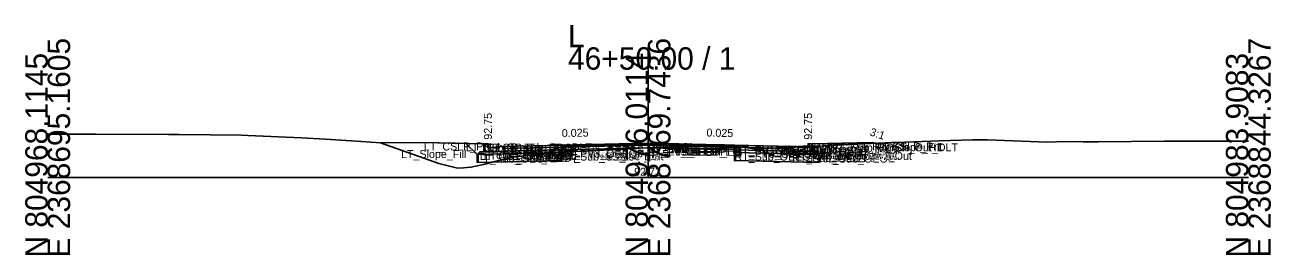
# Model space of a CAD drawing. Extents: x -26 to 8153, y -10 to 9520.
# Drawn here: x 3997.2 to 4152.8, y 3490.3 to 3519.1 of the extents above; entities that cross this region are included whole.
import ezdxf

# ---------------------------------------------------------------- set-up
doc = ezdxf.new("R2010")
doc.units = 0
for name, color, linetype in [('Exist CMT Pavement', 7, 'Continuous'), ('Exist Cross Section Cell', 7, 'Continuous'), ('Exist XS Center Line Elevation Label', 7, 'Continuous'), ('Exist XS Ground Line', 7, 'Continuous'), ('Prop CMT Conc Surface', 7, 'Continuous'), ('Prop CMT Concrete Structures', 7, 'Continuous'), ('Prop CMT Pvmt Course 1', 7, 'Continuous'), ('Prop CMT Pvmt Course 1 CG', 7, 'Continuous'), ('Prop CMT Pvmt Course 1 Wedge', 7, 'Continuous'), ('Prop CMT Pvmt Course 2', 7, 'Continuous'), ('Prop CMT Pvmt Course 2 Wedge', 7, 'Continuous'), ('Prop CMT Pvmt Course 3', 7, 'Continuous'), ('Prop CMT Pvmt Course 3 Wedge', 7, 'Continuous'), ('Prop CMT Pvmt Surface', 7, 'Continuous'), ('Prop CMT Pvmt Wedge Surface 1', 7, 'Continuous'), ('Prop CMT Pvmt Wedge Surface 2', 7, 'Continuous'), ('Prop CMT Pvmt Wedge Surface 3', 7, 'Continuous'), ('Prop CMT Shallow Undercut', 7, 'Continuous'), ('Prop CMT Shallow Undercut Boundary', 7, 'Continuous'), ('Prop CMT Slope Grass', 7, 'Continuous'), ('Prop CMT Subgrade Earthwork', 7, 'Continuous'), ('Prop XS Earthwork Shape', 7, 'Continuous'), ('Prop XS Hydro Elevations', 7, 'Continuous'), ('Prop XS SE Text', 7, 'Continuous'), ('Prop XS Side Slope Text', 7, 'Continuous'), ('Prop XS Subgrade Earthwork', 7, 'Continuous'), ('Scratch_Level_2', 7, 'Continuous'), ('Scratch_Level_5', 7, 'Continuous'), ('Scratch_Level_6', 7, 'Continuous')]:
    doc.layers.add(name, color=color, linetype=linetype)

msp = doc.modelspace()

# ---------------------------------------------------------------- linework, layer by layer
at = {"layer": 'Exist CMT Pavement'}
for p, q in [((4064.2, 3503.18), (4070.31, 3503.47)), ((4070.31, 3503.47), (4074.83, 3503.72)), ((4074.83, 3503.72), (4081.98, 3503.93)), ((4081.98, 3503.93), (4085.8, 3504))]:
    msp.add_line(p, q, dxfattribs=at)
at = {"layer": 'Exist Cross Section Cell'}
for p, q in [((4075, 3500), (4075, 3516.31)), ((4000, 3500), (4075, 3500)), ((4075, 3500), (4150, 3500))]:
    msp.add_line(p, q, dxfattribs=at)
at = {"layer": 'Exist XS Ground Line'}
for p, q in [((4000, 3505.44), (4004.88, 3505.42)), ((4004.88, 3505.42), (4005.99, 3505.42)), ((4005.99, 3505.42), (4015.08, 3505.39)), ((4015.08, 3505.39), (4016.44, 3505.38)), ((4016.44, 3505.38), (4024.18, 3505.3)), ((4024.18, 3505.3), (4025, 3505.29)), ((4025, 3505.29), (4031.71, 3504.96)), ((4031.71, 3504.96), (4034.66, 3504.83)), ((4034.66, 3504.83), (4037.96, 3504.59)), ((4037.96, 3504.59), (4041.56, 3504.36)), ((4096.93, 3504), (4105.45, 3504.41)), ((4105.45, 3504.41), (4106.02, 3504.4)), ((4106.02, 3504.4), (4111.41, 3504.62)), ((4111.41, 3504.62), (4115.55, 3504.75)), ((4115.55, 3504.75), (4117.4, 3504.75)), ((4117.4, 3504.75), (4124.88, 3504.44)), ((4124.88, 3504.44), (4127.26, 3504.51)), ((4127.26, 3504.51), (4129.36, 3504.5)), ((4129.36, 3504.5), (4131.25, 3504.47)), ((4131.25, 3504.47), (4139.53, 3504.57)), ((4139.53, 3504.57), (4141.49, 3504.57)), ((4141.49, 3504.57), (4150, 3504.55)), ((4041.56, 3504.36), (4047.69, 3502.18)), ((4060.23, 3502.8), (4064.2, 3503.18)), ((4064.2, 3503.18), (4070.31, 3503.47)), ((4070.31, 3503.47), (4074.83, 3503.72)), ((4074.83, 3503.72), (4081.98, 3503.93)), ((4081.98, 3503.93), (4085.8, 3504)), ((4085.8, 3504), (4088.28, 3503.61)), ((4088.28, 3503.61), (4088.58, 3503.58)), ((4088.58, 3503.58), (4094.39, 3503.94)), ((4094.39, 3503.94), (4095.39, 3503.95)), ((4095.39, 3503.95), (4096.93, 3504)), ((4047.69, 3502.18), (4048.86, 3501.77)), ((4048.86, 3501.77), (4051.2, 3501.18)), ((4051.97, 3501.22), (4052.87, 3501.3)), ((4052.87, 3501.3), (4054.43, 3501.66)), ((4054.43, 3501.66), (4057.83, 3502.53)), ((4057.83, 3502.53), (4060.23, 3502.8)), ((4051.2, 3501.18), (4051.97, 3501.22))]:
    msp.add_line(p, q, dxfattribs=at)
at = {"layer": 'Prop CMT Conc Surface'}
for points in [[(4055, 3503.75), (4055, 3504.25), (4054.5, 3504.25)], [(4057, 3503.88), (4055, 3503.75)], [(4093, 3503.88), (4095, 3503.75)], [(4095, 3503.75), (4095, 3504.25), (4095.5, 3504.25)]]:
    msp.add_lwpolyline(points, dxfattribs=at)
at = {"layer": 'Prop CMT Concrete Structures'}
for points in [[(4057, 3503.88), (4055, 3503.75), (4055, 3504.25), (4054.5, 3504.25)], [(4054.5, 3504.25), (4054.5, 3503.23), (4057, 3503.29)], [(4057, 3503.29), (4057, 3503.88)], [(4093, 3503.88), (4095, 3503.75), (4095, 3504.25), (4095.5, 3504.25)], [(4095.5, 3504.25), (4095.5, 3503.23), (4093, 3503.29)], [(4093, 3503.29), (4093, 3503.88)]]:
    msp.add_lwpolyline(points, dxfattribs=at)
at = {"layer": 'Prop CMT Pvmt Course 1'}
for points in [[(4075, 3504.33), (4057, 3503.88)], [(4057, 3503.88), (4057, 3503.63)], [(4057, 3503.63), (4064.2, 3503.81)], [(4064.2, 3503.93), (4075, 3504.2)], [(4064.2, 3503.81), (4064.2, 3503.93)], [(4075, 3504.08), (4075, 3504.33)], [(4075, 3504.33), (4093, 3503.88)], [(4075, 3504.08), (4075, 3504.33)], [(4075, 3504.2), (4075, 3504.08), (4075, 3504.08)], [(4085.8, 3503.93), (4075, 3504.2)], [(4075, 3504.2), (4075, 3504.08), (4075, 3504.08)], [(4085.8, 3503.81), (4085.8, 3503.93)], [(4093, 3503.63), (4085.8, 3503.81)], [(4093, 3503.88), (4093, 3503.63)]]:
    msp.add_lwpolyline(points, dxfattribs=at)
at = {"layer": 'Prop CMT Pvmt Course 1 CG'}
for points in [[(4057, 3503.29), (4054, 3503.22), (4053.66, 3502.88)], [(4053.66, 3502.88), (4057, 3502.96)], [(4057, 3502.96), (4057, 3503.29)], [(4093, 3503.29), (4096, 3503.22), (4096.34, 3502.88)], [(4093, 3502.96), (4093, 3503.29)], [(4096.34, 3502.88), (4093, 3502.96)]]:
    msp.add_lwpolyline(points, dxfattribs=at)
at = {"layer": 'Prop CMT Pvmt Course 1 Wedge'}
for points in [[(4075, 3504.2), (4064.2, 3503.93)], [(4075, 3504.2), (4085.8, 3503.93)]]:
    msp.add_lwpolyline(points, dxfattribs=at)
at = {"layer": 'Prop CMT Pvmt Course 2'}
for points in [[(4064.2, 3503.81), (4057, 3503.63)], [(4057, 3503.63), (4057, 3503.3)], [(4057, 3503.3), (4064.2, 3503.48)], [(4064.2, 3503.48), (4064.2, 3503.81)], [(4085.8, 3503.48), (4085.8, 3503.81)], [(4085.8, 3503.81), (4093, 3503.63)], [(4093, 3503.3), (4085.8, 3503.48)], [(4093, 3503.63), (4093, 3503.3)]]:
    msp.add_lwpolyline(points, dxfattribs=at)
at = {"layer": 'Prop CMT Pvmt Course 2 Wedge'}
for points in [[(4075, 3504.08), (4064.2, 3503.81)], [(4075, 3504.08), (4085.8, 3503.81)]]:
    msp.add_lwpolyline(points, dxfattribs=at)
at = {"layer": 'Prop CMT Pvmt Course 3'}
for points in [[(4064.2, 3503.48), (4057, 3503.3)], [(4057, 3503.3), (4057, 3502.96)], [(4057, 3502.96), (4064.2, 3503.14)], [(4064.2, 3503.14), (4064.2, 3503.48)], [(4085.8, 3503.48), (4093, 3503.3)], [(4085.8, 3503.14), (4085.8, 3503.48)], [(4093, 3502.96), (4085.8, 3503.14)], [(4093, 3503.3), (4093, 3502.96)]]:
    msp.add_lwpolyline(points, dxfattribs=at)
at = {"layer": 'Prop CMT Pvmt Course 3 Wedge'}
for points in [[(4075, 3503.75), (4064.2, 3503.48)], [(4075, 3503.75), (4085.8, 3503.48)]]:
    msp.add_lwpolyline(points, dxfattribs=at)
at = {"layer": 'Prop CMT Pvmt Surface'}
for points in [[(4075, 3504.33), (4057, 3503.88)], [(4075, 3504.33), (4093, 3503.88)]]:
    msp.add_lwpolyline(points, dxfattribs=at)
at = {"layer": 'Prop CMT Pvmt Wedge Surface 1'}
for points in [[(4057, 3503.63), (4057, 3503.88)], [(4064.2, 3503.81), (4057, 3503.63)], [(4075, 3504.2), (4064.2, 3503.93)], [(4064.2, 3503.93), (4064.2, 3503.81)], [(4075, 3504.2), (4085.8, 3503.93)], [(4085.8, 3503.93), (4085.8, 3503.81)], [(4085.8, 3503.81), (4093, 3503.63)], [(4093, 3503.63), (4093, 3503.88)]]:
    msp.add_lwpolyline(points, dxfattribs=at)
at = {"layer": 'Prop CMT Pvmt Wedge Surface 2'}
for points in [[(4075, 3504.08), (4057, 3503.63)], [(4057, 3503.63), (4057, 3503.88)], [(4075, 3504.08), (4093, 3503.63)], [(4093, 3503.63), (4093, 3503.88)]]:
    msp.add_lwpolyline(points, dxfattribs=at)
at = {"layer": 'Prop CMT Pvmt Wedge Surface 3'}
for points in [[(4057, 3503.3), (4057, 3503.88)], [(4075, 3503.75), (4057, 3503.3)], [(4075, 3503.75), (4093, 3503.3)], [(4093, 3503.3), (4093, 3503.88)]]:
    msp.add_lwpolyline(points, dxfattribs=at)
at = {"layer": 'Prop CMT Shallow Undercut'}
for p, q in [((4085.8, 3503.14), (4085.8, 3502.14)), ((4096.34, 3502.88), (4085.8, 3503.14)), ((4096.34, 3501.88), (4096.34, 3502.88)), ((4085.8, 3502.14), (4096.34, 3501.88))]:
    msp.add_line(p, q, dxfattribs=at)
msp.add_lwpolyline([(4055.47, 3501.93), (4064.2, 3502.14), (4064.2, 3503.14), (4063.68, 3503.13), (4060.23, 3502.8), (4057.83, 3502.53)], close=True, dxfattribs=at)
at = {"layer": 'Prop CMT Shallow Undercut Boundary'}
for p, q in [((4053.66, 3502.88), (4053.66, 3501.88)), ((4064.2, 3503.14), (4064.2, 3502.14)), ((4085.8, 3503.14), (4085.8, 3502.14)), ((4096.34, 3502.88), (4096.34, 3501.88)), ((4053.66, 3501.88), (4064.2, 3502.14)), ((4085.8, 3502.14), (4096.34, 3501.88))]:
    msp.add_line(p, q, dxfattribs=at)
at = {"layer": 'Prop CMT Slope Grass'}
for points in [[(4054.5, 3504.25), (4047, 3504.4), (4041.56, 3504.36)], [(4095.5, 3504.25), (4103, 3504.4), (4103.28, 3504.3)]]:
    msp.add_lwpolyline(points, dxfattribs=at)
at = {"layer": 'Prop CMT Subgrade Earthwork'}
for points in [[(4057, 3502.96), (4053.66, 3502.88), (4052.25, 3504.29)], [(4064.2, 3503.14), (4057, 3502.96)], [(4064.2, 3503.14), (4064.22, 3503.18)], [(4085.8, 3503.14), (4085.78, 3504)], [(4085.8, 3503.14), (4093, 3502.96)], [(4093, 3502.96), (4096.34, 3502.88), (4097.75, 3504.29)]]:
    msp.add_lwpolyline(points, dxfattribs=at)
at = {"layer": 'Prop XS Earthwork Shape'}
for points in [[(4047.69, 3502.18), (4048.86, 3501.77), (4051.2, 3501.18), (4051.97, 3501.22), (4052.87, 3501.3), (4054.43, 3501.66), (4055.47, 3501.93), (4053.66, 3501.88), (4053.66, 3502.88), (4052.25, 3504.29), (4047, 3504.4), (4041.56, 3504.36)], [(4103, 3504.4), (4103.28, 3504.3), (4097.48, 3504.03), (4097.75, 3504.29)], [(4057.83, 3502.53), (4060.23, 3502.8), (4063.68, 3503.13), (4057, 3502.96), (4053.66, 3502.88), (4053.66, 3501.88), (4055.47, 3501.93)], [(4057.83, 3502.53), (4060.23, 3502.8), (4063.68, 3503.13), (4064.2, 3503.14), (4064.2, 3502.14), (4055.47, 3501.93)], [(4064.2, 3503.14), (4063.68, 3503.13), (4064.2, 3503.18), (4064.22, 3503.18)], [(4093.18, 3503.87), (4095, 3503.75), (4095, 3503.95), (4095.39, 3503.95), (4096.93, 3504), (4097.48, 3504.03), (4096.34, 3502.88), (4093, 3502.96), (4085.8, 3503.14), (4085.78, 3504), (4085.8, 3504), (4088.28, 3503.61), (4088.58, 3503.58)], [(4096.34, 3502.88), (4096.34, 3501.88), (4085.8, 3502.14), (4085.8, 3503.14), (4093, 3502.96)], [(4093.18, 3503.87), (4095, 3503.75), (4095, 3503.95), (4094.39, 3503.94)]]:
    msp.add_lwpolyline(points, close=True, dxfattribs=at)
at = {"layer": 'Prop XS Subgrade Earthwork'}
for p, q in [((4053.66, 3502.88), (4064.2, 3503.14)), ((4085.8, 3503.14), (4096.34, 3502.88))]:
    msp.add_line(p, q, dxfattribs=at)
at = {"layer": 'Scratch_Level_5'}
for p, q in [((4054.5, 3504.25), (4052.25, 3504.29)), ((4052.25, 3504.29), (4053.66, 3502.88)), ((4053.66, 3502.88), (4054, 3503.22)), ((4054, 3503.22), (4054.5, 3503.23)), ((4054.5, 3503.23), (4054.5, 3504.25)), ((4097.75, 3504.29), (4095.5, 3504.25)), ((4095.5, 3504.25), (4095.5, 3503.23)), ((4095.5, 3503.23), (4096, 3503.22)), ((4096, 3503.22), (4096.34, 3502.88)), ((4096.34, 3502.88), (4097.75, 3504.29))]:
    msp.add_line(p, q, dxfattribs=at)
at = {"layer": 'Scratch_Level_6'}
for p, q in [((4085.8, 3503.14), (4085.8, 3502.14)), ((4096.34, 3502.88), (4085.8, 3503.14)), ((4096.34, 3501.88), (4096.34, 3502.88)), ((4085.8, 3502.14), (4096.34, 3501.88))]:
    msp.add_line(p, q, dxfattribs=at)
msp.add_lwpolyline([(4055.47, 3501.93), (4064.2, 3502.14), (4064.2, 3503.14), (4063.68, 3503.13), (4060.23, 3502.8), (4057.83, 3502.53)], close=True, dxfattribs=at)

# ---------------------------------------------------------------- texts
at = {"layer": 'Exist Cross Section Cell'}
for s, p in [('L', (4065, 3516.31)), ('46+50.00 / 1', (4065, 3513.51))]:
    msp.add_text(s, height=2.8, dxfattribs=at).set_placement(p)
for s, p in [('E 2368695.1605', (4002.8, 3490)), ('E 2368769.7436', (4077.8, 3490)), ('E 2368844.3267', (4152.8, 3490)), ('N 804968.1145', (4000, 3490)), ('N 804976.0114', (4075, 3490)), ('N 804983.9083', (4150, 3490))]:
    msp.add_text(s, height=2.8, rotation=90, dxfattribs=at).set_placement(p)
at = {"layer": 'Exist XS Center Line Elevation Label'}
msp.add_text('92.73', height=1, dxfattribs=at).set_placement((4073.27, 3500.23))
at = {"layer": 'Prop XS Hydro Elevations'}
for p in [(4055.5, 3504.75), (4095.5, 3504.75)]:
    msp.add_text('92.75', height=1, rotation=90, dxfattribs=at).set_placement(p)
at = {"layer": 'Prop XS SE Text'}
for rotation, p in [(1.4321, (4064.24, 3505.06)), (358.5679, (4082.29, 3505.15))]:
    msp.add_text('0.025', height=1, rotation=rotation, dxfattribs=at).set_placement(p)
at = {"layer": 'Prop XS Side Slope Text'}
msp.add_text('3:1', height=1, rotation=341.5651, dxfattribs=at).set_placement((4102.63, 3505.31))
at = {"layer": 'Scratch_Level_2'}
for s, p in [('LT_CSLP_Pnt', (4047, 3503.4)), ('RT_CSLP_Pnt', (4103, 3503.4)), ('LT_Slope_Fill', (4044.14, 3502.45)), ('LT_Sub_Trench_Out_DLT', (4052.25, 3503.29)), ('LT_Sub_OEOP', (4053.66, 3501.88)), ('LT_CG1_Shelf_Out', (4054, 3502.22)), ('LT_CG_Top_BOC', (4054.5, 3503.25)), ('LT_CG_Bot_BOC', (4054.5, 3502.23)), ('LT_CG_Top_Face', (4055, 3503.25)), ('LT_CG_Top_Gut', (4055, 3502.75)), ('LT_PV1_OEOT', (4057, 3502.88)), ('LT_PV2_OEOT', (4057, 3502.63)), ('LT_PV3_OEOT', (4057, 3502.3)), ('LT_CG_Bot_IE', (4057, 3502.29)), ('LT_Sub_OEOT', (4057, 3501.96)), ('LT_PV1_OEEOP', (4064.2, 3502.93)), ('LT_PV2_OEEOP', (4064.2, 3502.81)), ('LT_PV3_OEEOP', (4064.2, 3502.48)), ('LT_PV_OEEOP_EG', (4064.2, 3502.18)), ('LT_Sub_OEEOP', (4064.2, 3502.14)), ('LT_PV_Sub_Tie_Out', (4064.22, 3502.18)), ('PV1_PGL', (4075, 3503.33)), ('RT_PV1_IEEOP', (4075, 3503.2)), ('LT_PV1_IEEOP', (4075, 3503.2)), ('RT_PV2_IEEOP', (4075, 3503.08)), ('LT_PV2_IEEOP', (4075, 3503.08)), ('PV2_PGL', (4075, 3503.08)), ('RT_PV3_IEEOP', (4075, 3502.75)), ('LT_PV3_IEEOP', (4075, 3502.75)), ('RT_PV_IEEOP_EG', (4075, 3502.73)), ('LT_PV_IEEOP_EG', (4075, 3502.73)), ('RT_PV_Sub_Tie_Out', (4085.78, 3503)), ('RT_PV_OEEOP_EG', (4085.8, 3503)), ('RT_PV1_OEEOP', (4085.8, 3502.93)), ('RT_PV2_OEEOP', (4085.8, 3502.81)), ('RT_PV3_OEEOP', (4085.8, 3502.48)), ('RT_Sub_OEEOP', (4085.8, 3502.14)), ('RT_PV1_OEOT', (4093, 3502.88)), ('RT_PV2_OEOT', (4093, 3502.63)), ('RT_PV3_OEOT', (4093, 3502.3)), ('RT_CG_Bot_IE', (4093, 3502.29)), ('RT_Sub_OEOT', (4093, 3501.96)), ('RT_CG_Top_Face', (4095, 3503.25)), ('RT_CG_Top_Gut', (4095, 3502.75)), ('RT_CG_Top_BOC', (4095.5, 3503.25)), ('RT_CG_Bot_BOC', (4095.5, 3502.23)), ('RT_CG1_Shelf_Out', (4096, 3502.22)), ('RT_Sub_OEOP', (4096.34, 3501.88)), ('RT_Sub_Trench_Out_DLT', (4097.75, 3503.29)), ('RT_Slope_Fill', (4103.28, 3503.3))]:
    msp.add_text(s, height=1, dxfattribs=at).set_placement(p)

doc.saveas('drawing.dxf')
